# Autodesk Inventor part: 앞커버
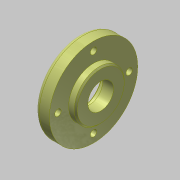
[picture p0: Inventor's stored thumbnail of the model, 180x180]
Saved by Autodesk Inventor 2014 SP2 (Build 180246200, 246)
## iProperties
Created: 2015-12
Part Number: 앞커버
Document SubType Name: Modeling
Designer: mdu
Density: 2.71 g/cm^3
Material: 알루미늄 6061
Mass: 70.9323 g
Surface Area: 93.9278 cm^2
Volume: 26.1743 cm^3
Appearance: 널링 45
Author: mdu
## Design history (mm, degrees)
sketch "스케치1"
  geometry: L1 (-7.5, 0)-(7.5, 0); L2 (-7.5, 0)-(-7.5, 31); L3 (-7.5, 31)-(2.5, 31); L4 (2.5, 31)-(2.5, 17.5); L5 (2.5, 17.5)-(7.5, 17.5); L6 (7.5, 17.5)-(7.5, 0); 2 further points
  constraints: 12 end point, 3 perpendicular, 1 coincident, 1 horizontal, 1 midpoint, 1 parallel
  dimensions: "d0" = 15 distance of L1.start L1.end; "d1" = 62 diameter of L3 L1; "d2" = 35 diameter of L5 L1; "d5" = 10 distance of L2.end L3.end
revolve "회전1" sketch "스케치1" stored, may be unused: angle "d6" = 90 deg
sketch "스케치2" dims "d42" = 50
  geometry: 3 further points
  constraints: 2 vertical alignment, 1 coincident, 2 other
hole "구멍1" sketch "스케치2" at (0, 25) diameter "d8" = 4.5; stored, may be unused: countersink angle "d12" = 90 deg, drill point angle "d14" = 118 deg; dims "d9" = 6, "d10" = 8, "d11" = 4.4, "d13" = 8
hole "구멍2" diameter "d20" = 18; stored, may be unused: countersink angle "d24" = 90 deg, drill point angle "d26" = 0 deg; dims "d18" = 10, "d19" = 10, "d21" = 6, "d22" = 8, "d23" = 4.4, "d25" = 8
hole "구멍3" diameter "d34" = 30; stored, may be unused: countersink angle "d38" = 90 deg, drill point angle "d40" = 0 deg; dims "d32" = 10, "d33" = 10, "d35" = 6, "d36" = 4, "d37" = 2, "d39" = 7.3
fillet "모깎기1" dims "d27" = 3, "d41" = 0.3
chamfer "모따기1" distance "d29" = 1; stored, may be unused: second distance "d30" = 2, angle "d31" = 45 deg
node "솔리드1"
pattern_circular "원형 패턴1" dims angle "d16" = 360 deg
